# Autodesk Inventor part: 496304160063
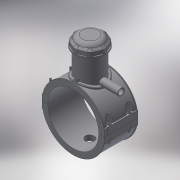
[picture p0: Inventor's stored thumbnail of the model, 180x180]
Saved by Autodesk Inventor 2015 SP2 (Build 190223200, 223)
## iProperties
Created: 2017-07
Part Number: 496304160063
Material: Generic
Description: PLASSON TAPPING SADDLE 160x63
Document SubType Name: Modeling
Designer: KIM
Mass: 1160.03 g
Surface Area: 2667.3 cm^2
Volume: 1160.03 cm^3
Density: 1 g/cm^3
Appearance: Default
Author: KIM
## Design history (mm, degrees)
derived "496304.ipt"
feature "Solid1::496304.ipt"
feature "Solid2::496304.ipt"
feature "Solid4::496304.ipt"
feature "Solid5::496304.ipt"
tag "TaggingFeature1"
body "Solid1"
body "Solid2"
other parameters: "B_" = 199, "L_" = 118, "d_t" = 6, "H_2" = 138, "d_1" = 63, "H_" = 197, "d1" = 182.4, "d148" = 2.4, "d160" = 2.4, "d169" = 3.375, "d192" = 6.3, "d2" = 199, "d4" = 118, "d5" = 0, "d6" = 0.1, "d8" = 0, "d19" = 6, "d20" = 6, "d21" = 70.8, "d23" = 0, "d24" = 35.4, "d26" = 0, "d29" = 3, "d30" = 53.33333, "d31" = 6, "d32" = 0, "d33" = 0, "d34" = 0.6, "d40" = 94.848, "d41" = 72, "d43" = 0, "d45" = 0, "d47" = 162, "d70" = 15, "d72" = 0, "d73" = 6, "d75" = 5, "d76" = 0, "d77" = 8, "d79" = 15, "d80" = 47.2, "d82" = 5 deg, "d84" = 4, "d85" = 14, "d86" = 0, "d87" = 3, "d88" = 0, "d89" = 1, "d90" = 1, "d91" = 94.4, "d92" = 0, "d93" = 0.5, "d94" = 84.21053, "d96" = 186.048, "d97" = 2.36, "d98" = 0, "d102" = 1.6, "d120" = 140 deg, "d121" = 24.228, "d122" = 20 deg, "d123" = 364.8, "d124" = 109.44, "d126" = 0, "d143" = 164.8, "d145" = 17.23077, "d149" = 2.4, "d150" = 18.95385, "d153" = 118, "d154" = 0, "d156" = 91.2, "d157" = 160 deg, "d159" = 4.48, "d161" = 2.4, "d162" = 70.8, "d163" = 0, "d167" = 16, "d168" = 88.97561, "d170" = 3.375, "d172" = 0, "d173" = 1, "d176" = 20 deg, "d177" = 11.2, "d178" = 22.4, "d180" = 0, "d183" = 8.96, "d184" = 8.96, "d185" = 38.35, "d186" = 38.35, "d187" = 91.2, "d188" = 6.72, "d189" = 11.2, "d190" = 0, "d191" = 136.8, "d193" = 6.3, "d194" = 4.13, "d195" = 90 deg, "d197" = 0, "d199" = 0, "d200" = 11.2, "d202" = 0, "d203" = 138, "d204" = 68.4, "d205" = 50.4, "d206" = 61.2, "d207" = 103.5, "d208" = 107.64, "d209" = 128.34, "d210" = 61.92, "d211" = 72, "d212" = 57.6, "d213" = -10.35, "d216" = 0, "d217" = 16, "d218" = 16, "d219" = 3.2, "d224" = 0, "d230" = 3.2, "d233" = 6, "d236" = 99.5, "d237" = 35.4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
